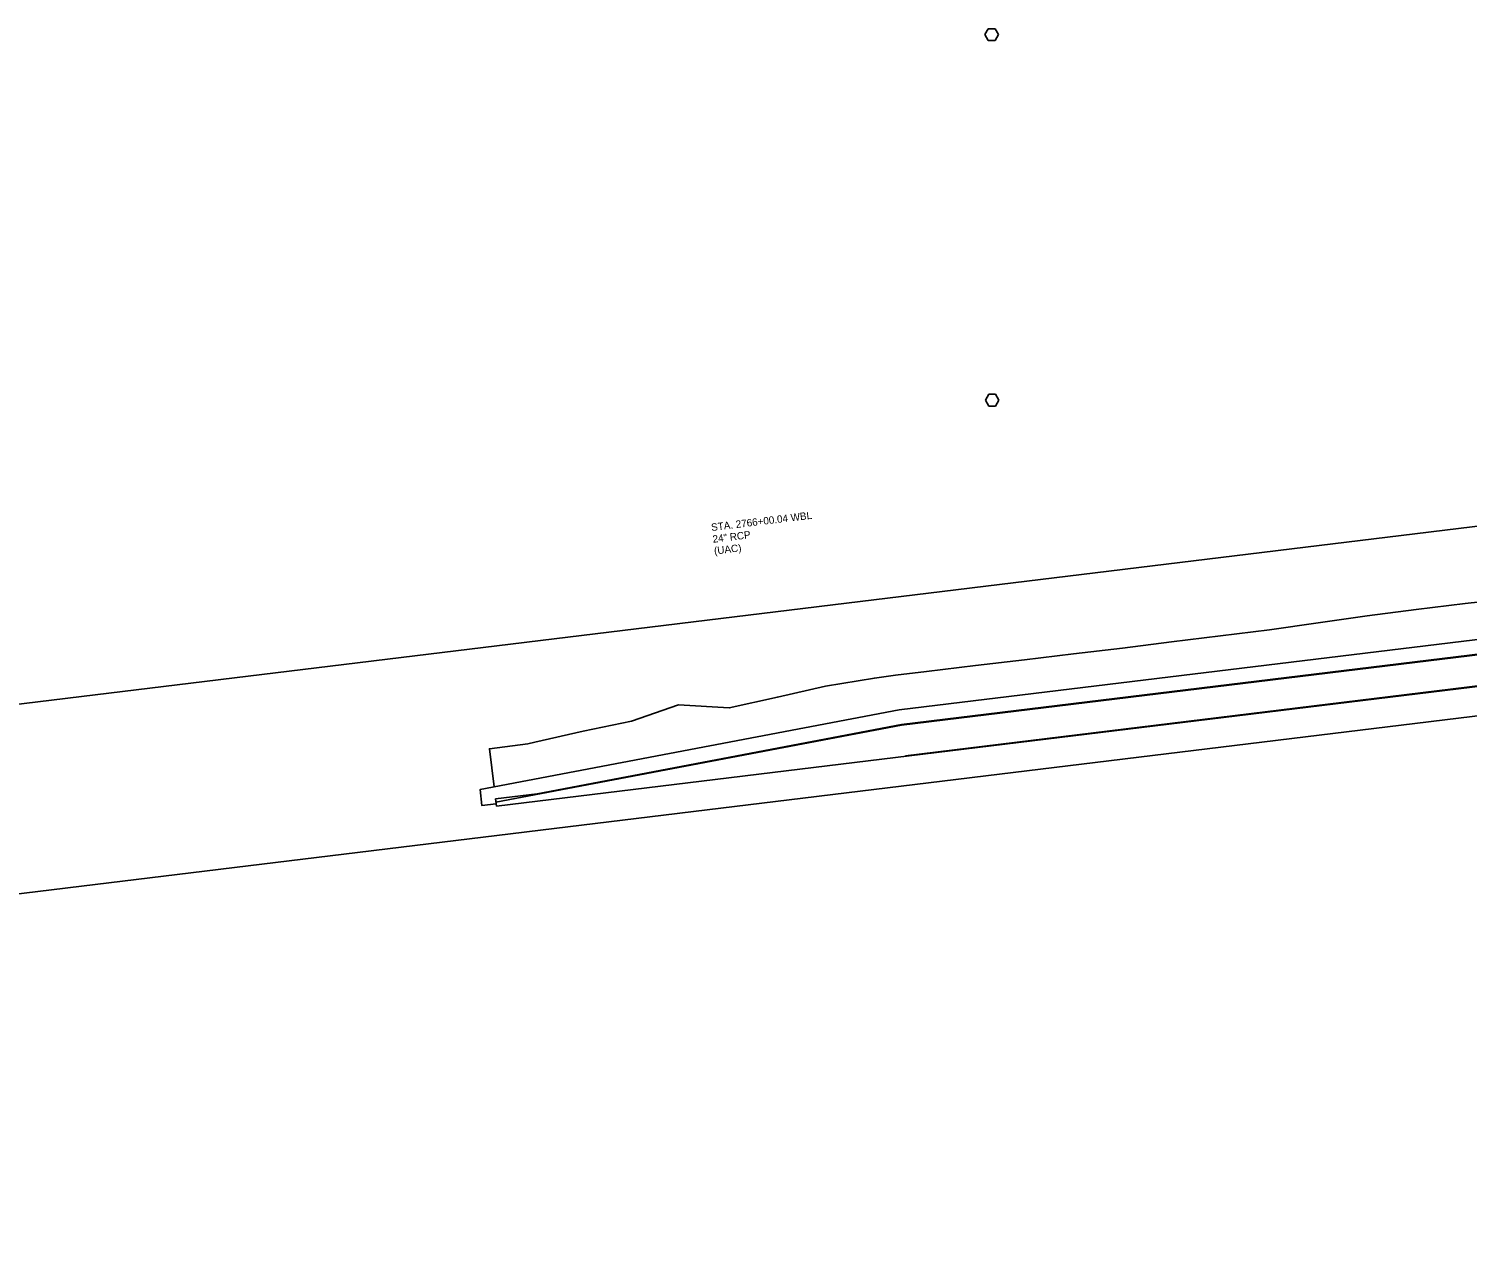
# Model space of a CAD drawing. Extents: x 18436148 to 18440034, y 7649939 to 7652226.
# Drawn here: x 18437374 to 18437957, y 7649939 to 7650437 of the extents above; entities that cross this region are included whole.
import ezdxf

# ---------------------------------------------------------------- set-up
doc = ezdxf.new("R2010")
doc.units = 0
for name, color, linetype in [('ATVEHICLE', 7, 'Continuous'), ('Drainage', 7, 'Continuous'), ('ROWTitleBlock', 7, 'Continuous'), ('TL_ShoulderBtm', 7, 'Continuous'), ('TSOUTLINE', 7, 'Continuous'), ('TSWHEELBASE', 7, 'Continuous')]:
    doc.layers.add(name, color=color, linetype=linetype)

msp = doc.modelspace()

# ---------------------------------------------------------------- linework, layer by layer
at = {"layer": 'ATVEHICLE'}
for p, q in [((18438432.51, 7650227.61), (18437563.42, 7650121.72)), ((18438276.57, 7650221.71), (18437727.63, 7650154.82)), ((18437727.63, 7650154.82), (18437579.94, 7650126.75)), ((18437579.94, 7650126.75), (18437563.06, 7650124.69)), ((18437563.06, 7650124.69), (18437563.42, 7650121.72))]:
    msp.add_line(p, q, dxfattribs=at)
at = {"layer": 'Drainage'}
for p, q in [((18437761.4, 7650434.28), (18437762.77, 7650436.66)), ((18437762.77, 7650436.66), (18437765.52, 7650436.66)), ((18437765.52, 7650436.66), (18437766.9, 7650434.28)), ((18437762.77, 7650431.9), (18437761.4, 7650434.28)), ((18437765.52, 7650431.9), (18437762.77, 7650431.9)), ((18437766.9, 7650434.28), (18437765.52, 7650431.9)), ((18437761.6, 7650286.23), (18437762.97, 7650288.61)), ((18437762.97, 7650283.84), (18437761.6, 7650286.23)), ((18437762.97, 7650288.61), (18437765.72, 7650288.61)), ((18437765.72, 7650283.84), (18437762.97, 7650283.84)), ((18437765.72, 7650288.61), (18437767.1, 7650286.23)), ((18437767.1, 7650286.23), (18437765.72, 7650283.84))]:
    msp.add_line(p, q, dxfattribs=at)
at = {"layer": 'TL_ShoulderBtm'}
for p, q in [((18438530.78, 7650304.56), (18436148.4, 7650014.28)), ((18438540.01, 7650228.87), (18436157.63, 7649938.59)), ((18437727.66, 7650154.57), (18438276.6, 7650221.46)), ((18438278.11, 7650209.05), (18437729.19, 7650142.17)), ((18437563.23, 7650123.32), (18437727.66, 7650154.57))]:
    msp.add_line(p, q, dxfattribs=at)
at = {"layer": 'TSOUTLINE'}
msp.add_lwpolyline([(18437563.42, 7650121.72), (18437563.3, 7650122.71), (18437557.49, 7650122.06), (18437556.77, 7650128.45), (18437562.47, 7650129.54), (18437560.59, 7650145), (18437576.09, 7650147.02), (18437579.01, 7650147.7), (18437598.54, 7650152.05), (18437618.12, 7650156.15), (18437637.21, 7650162.79), (18437657.81, 7650161.56), (18437677.33, 7650165.95), (18437696.86, 7650170.3), (18437716.62, 7650173.61), (18437725.19, 7650174.84), (18437737.77, 7650176.26), (18437757.63, 7650178.67), (18437777.49, 7650181.06), (18437797.35, 7650183.39), (18437817.2, 7650185.79), (18437837.05, 7650188.31), (18437856.9, 7650190.76), (18437876.76, 7650193.11), (18437896.55, 7650195.98), (18437916.35, 7650198.84), (18437936.18, 7650201.45), (18437956.04, 7650203.83), (18437995.83, 7650208.21)], dxfattribs=at)
at = {"layer": 'TSWHEELBASE'}
for p, q in [((18438275.84, 7650227.66), (18437726.7, 7650160.75)), ((18437726.7, 7650160.75), (18437556.77, 7650128.45)), ((18437556.77, 7650128.45), (18437557.49, 7650122.06)), ((18437557.49, 7650122.06), (18437563.3, 7650122.71))]:
    msp.add_line(p, q, dxfattribs=at)

# ---------------------------------------------------------------- texts
at = {"layer": 'ROWTitleBlock'}
for s, p in [('STA. 2766+00.04 WBL', (18437650.65, 7650233.18)), ('24" RCP', (18437651.23, 7650228.42)), ('(UAC)', (18437651.81, 7650223.65))]:
    msp.add_text(s, height=3, rotation=6.94701, dxfattribs=at).set_placement(p)

doc.saveas('drawing.dxf')
